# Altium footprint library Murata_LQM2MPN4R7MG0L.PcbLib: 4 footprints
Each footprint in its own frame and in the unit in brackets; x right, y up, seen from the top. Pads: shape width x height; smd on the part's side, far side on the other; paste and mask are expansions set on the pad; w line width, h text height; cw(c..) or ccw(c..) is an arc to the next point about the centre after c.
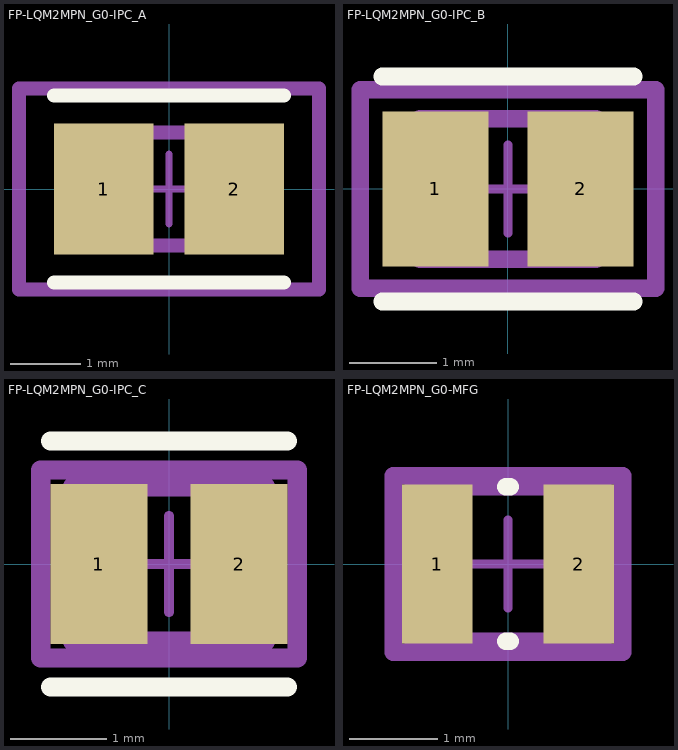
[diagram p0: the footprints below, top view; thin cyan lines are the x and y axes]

## FP-LQM2MPN_G0-IPC_A [mm]
pads (2):
  rect 1.406x1.858 smd paste+0 mask+0: 1(-0.926,0) 2(0.926,0)
Top Overlay:
  lines w0.2: -1.629,-1.329 1.629,-1.329 ; -1.629,1.329 1.629,1.329
Top Assembly:
  lines w0.2: -2.129,-1.429 2.129,-1.429 2.129,1.429 -2.129,1.429 -2.129,-1.429
  text ".Designator" at 0,0.188 h1
Top 3D Body:
  lines w0.2: -1,-0.8 1,-0.8 1,0.8 -1,0.8 -1,-0.8
Top Courtyard:
  lines w0.2: -2.129,-1.429 2.129,-1.429 2.129,1.429 -2.129,1.429 -2.129,-1.429
Top Component Center:
  lines w0.1: -0.5,0 0.5,0 ; 0,-0.5 0,0.5
3D body "Ind_Murata_LQM2MPN1R5MG0B_eec.STEP": height 0.25, standoff 0, extent -2.129,-1.429 2.129,1.429

## FP-LQM2MPN_G0-IPC_B [mm]
pads (2):
  rect 1.206x1.758 smd paste+0 mask+0: 1(-0.826,0) 2(0.826,0)
Top Overlay:
  lines w0.2: -1.429,-1.279 1.429,-1.279 ; -1.429,1.279 1.429,1.279
Top Assembly:
  lines w0.2: -1.679,-1.129 1.679,-1.129 1.679,1.129 -1.679,1.129 -1.679,-1.129
  text ".Designator" at 0,0.188 h1
Top 3D Body:
  lines w0.2: -1,-0.8 1,-0.8 1,0.8 -1,0.8 -1,-0.8
Top Courtyard:
  lines w0.2: -1.679,-1.129 1.679,-1.129 1.679,1.129 -1.679,1.129 -1.679,-1.129
Top Component Center:
  lines w0.1: -0.5,0 0.5,0 ; 0,-0.5 0,0.5
3D body "Ind_Murata_LQM2MPN1R5MG0B_eec.STEP": height 0.25, standoff 0, extent -1.679,-1.129 1.679,1.129

## FP-LQM2MPN_G0-IPC_C [mm]
pads (2):
  rect 1.006x1.658 smd paste+0 mask+0: 1(-0.726,0) 2(0.726,0)
Top Overlay:
  lines w0.2: -1.229,-1.275 1.229,-1.275 ; -1.229,1.275 1.229,1.275
Top Assembly:
  lines w0.2: -1.329,-0.975 1.329,-0.975 1.329,0.975 -1.329,0.975 -1.329,-0.975
  text ".Designator" at 0,0.188 h1
Top 3D Body:
  lines w0.2: -1,-0.8 1,-0.8 1,0.8 -1,0.8 -1,-0.8
Top Courtyard:
  lines w0.2: -1.329,-0.975 1.329,-0.975 1.329,0.975 -1.329,0.975 -1.329,-0.975
Top Component Center:
  lines w0.1: -0.5,0 0.5,0 ; 0,-0.5 0,0.5
3D body "Ind_Murata_LQM2MPN1R5MG0B_eec.STEP": height 0.25, standoff 0, extent -1.329,-0.975 1.329,0.975

## FP-LQM2MPN_G0-MFG [mm]
pads (2):
  rect 0.8x1.8 smd paste+0 mask+0: 1(-0.8,0) 2(0.8,0)
Top Overlay:
  lines w0.2: -0.025,-0.875 0.025,-0.875 ; -0.025,0.875 0.025,0.875
Top Assembly:
  lines w0.2: -1.3,-1 1.3,-1 1.3,1 -1.3,1 -1.3,-1
  text ".Designator" at 0,0.188 h1
Top 3D Body:
  lines w0.2: -1.075,-0.875 1.075,-0.875 1.075,0.875 -1.075,0.875 -1.075,-0.875
Top Courtyard:
  lines w0.2: -1.3,-1 1.3,-1 1.3,1 -1.3,1 -1.3,-1
Top Component Center:
  lines w0.1: -0.5,0 0.5,0 ; 0,-0.5 0,0.5
3D body "Ind_Murata_LQM2MPN1R5MG0B_eec.STEP": height 0.25, standoff 0, extent -1.3,-1 1.3,1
